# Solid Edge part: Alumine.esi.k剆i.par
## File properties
Author: Türk
Template: Iso Part.par
Last saved by: Türk
Revision: 1
Application: Solid Edge
Accuracy: 0,990
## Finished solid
Body 1: solid body, 20 faces, 39 edges, 20 vertices.
  Faces by surface: cylinder 14, plane 4, torus 2
  Edges by curve: intersection 16, circle 14, ellipse 7, line 2
Bounding box of the edges (mm; curved faces can reach further): 250.000 x 118.000 x 50.000, from (-225, 0, -25) to (25, 118, 25).
Cylindrical faces by radius (mm): R10.5 x2, R15 x10, R25 x2
Toroidal faces (ring radius, tube radius in mm): R400 r15 x2
Planar faces by outward normal: +y 2, -y 2
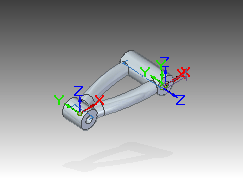
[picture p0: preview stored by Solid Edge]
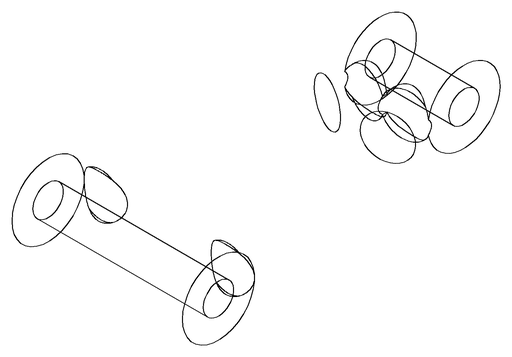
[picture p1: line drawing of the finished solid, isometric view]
